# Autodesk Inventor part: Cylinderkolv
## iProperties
Created: 2007-04
Part Number: Cylinderkolv
Document SubType Name: Modeling
Designer: kurs1
Density: 1 g/cm^3
Author: kurs1
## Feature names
1. Revolution1
